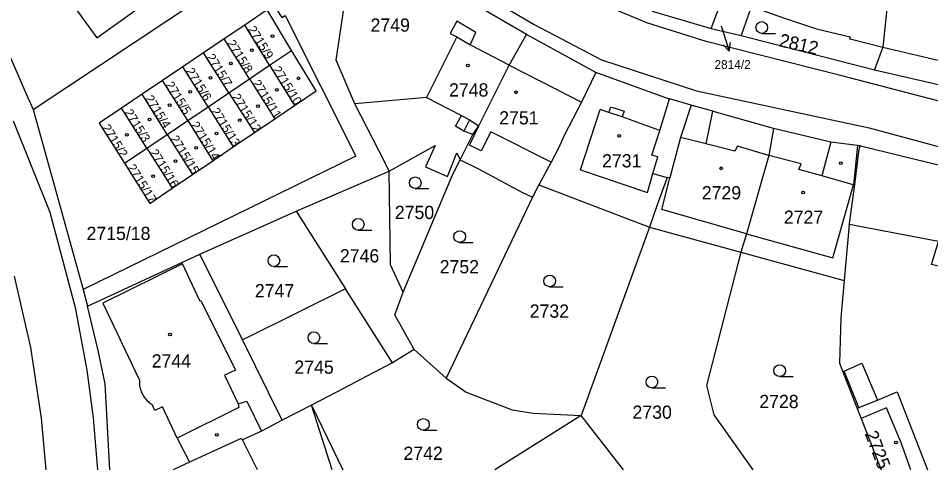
# Model space of a CAD drawing. Extents: x -527335 to -526256, y -1079142 to -1077809.
# Drawn here: x -527116.6 to -526999.4, y -1079141.5 to -1079083.6 of the extents above; entities that cross this region are included whole.
import ezdxf

# ---------------------------------------------------------------- set-up
doc = ezdxf.new("R2010")
doc.units = 0
for name, color, linetype in [('Vrstva 1', 7, 'Continuous'), ('Vrstva 2', 7, 'Continuous'), ('Vrstva 3', 7, 'Continuous'), ('Vrstva 4', 7, 'Continuous'), ('Vrstva 5', 7, 'Continuous'), ('Vrstva 7', 7, 'Continuous')]:
    doc.layers.add(name, color=color, linetype=linetype)

msp = doc.modelspace()

# ---------------------------------------------------------------- linework, layer by layer
at = {"layer": 'Vrstva 1'}
for p, q in [((-527027.56, -1079084.87), (-527026.14, -1079080.97)), ((-527035.15, -1079082.66), (-527027.56, -1079084.87)), ((-527022.5, -1079082.36), (-527023.73, -1079085.78)), ((-527087.52, -1079084.42), (-527090.18, -1079086.21)), ((-527084.33, -1079089.58), (-527087.52, -1079084.42)), ((-527027.56, -1079084.87), (-527023.73, -1079085.78)), ((-527090.18, -1079086.21), (-527092.83, -1079087.99)), ((-527086.93, -1079091.34), (-527090.18, -1079086.21)), ((-527053.53, -1079089.58), (-527051.3, -1079085.65)), ((-527042.41, -1079090.54), (-527051.3, -1079085.65)), ((-527023.73, -1079085.78), (-527006.59, -1079090.18)), ((-527084.33, -1079089.58), (-527081.51, -1079087.68)), ((-527092.83, -1079087.99), (-527095.49, -1079089.78)), ((-527089.56, -1079093.11), (-527092.83, -1079087.99)), ((-527095.49, -1079089.78), (-527098.1, -1079091.54)), ((-527092.24, -1079094.93), (-527095.49, -1079089.78)), ((-527086.93, -1079091.34), (-527084.33, -1079089.58)), ((-527084.33, -1079089.58), (-527081.13, -1079094.75)), ((-527089.56, -1079093.11), (-527086.93, -1079091.34)), ((-527086.93, -1079091.34), (-527083.68, -1079096.47)), ((-527098.1, -1079091.54), (-527100.72, -1079093.3)), ((-527094.86, -1079096.7), (-527098.1, -1079091.54)), ((-527100.72, -1079093.3), (-527103.37, -1079095.09)), ((-527097.49, -1079098.47), (-527100.72, -1079093.3)), ((-527092.24, -1079094.93), (-527089.56, -1079093.11)), ((-527089.56, -1079093.11), (-527086.28, -1079098.23)), ((-527083.68, -1079096.47), (-527081.13, -1079094.75)), ((-527114.75, -1079095.26), (-527108.32, -1079118.4)), ((-527100.12, -1079100.24), (-527103.37, -1079095.09)), ((-527094.86, -1079096.7), (-527092.24, -1079094.93)), ((-527092.24, -1079094.93), (-527089, -1079100.07)), ((-527097.49, -1079098.47), (-527094.86, -1079096.7)), ((-527094.86, -1079096.7), (-527091.63, -1079101.85)), ((-527086.28, -1079098.23), (-527083.68, -1079096.47)), ((-527089, -1079100.07), (-527086.28, -1079098.23)), ((-527100.12, -1079100.24), (-527097.49, -1079098.47)), ((-527097.49, -1079098.47), (-527094.26, -1079103.63)), ((-527102.99, -1079102.18), (-527100.12, -1079100.24)), ((-527100.12, -1079100.24), (-527096.87, -1079105.39)), ((-527091.63, -1079101.85), (-527089, -1079100.07)), ((-527094.26, -1079103.63), (-527091.63, -1079101.85)), ((-527096.87, -1079105.39), (-527094.26, -1079103.63)), ((-527080.91, -1079108.31), (-527068.95, -1079103.19)), ((-527049.72, -1079104.95), (-527050.56, -1079106.52)), ((-527049.72, -1079104.95), (-527035.52, -1079110.39)), ((-527050.56, -1079106.52), (-527061.66, -1079129.77)), ((-527080.91, -1079108.31), (-527074.57, -1079118.3)), ((-527009.82, -1079110.06), (-527010.5, -1079117.24)), ((-527035.52, -1079110.39), (-527044.28, -1079134.58)), ((-527035.52, -1079110.39), (-527023.76, -1079113.6)), ((-527023.76, -1079113.6), (-527010.5, -1079117.24)), ((-527107.73, -1079120.51), (-527093.31, -1079113.86)), ((-527087.83, -1079124.87), (-527093.31, -1079113.86)), ((-527068.54, -1079127.79), (-527074.57, -1079118.3)), ((-527108.32, -1079118.4), (-527107.73, -1079120.51)), ((-527082.7, -1079135.19), (-527087.83, -1079124.87)), ((-527065.77, -1079126.11), (-527068.54, -1079127.79)), ((-527061.66, -1079129.77), (-527065.77, -1079126.11)), ((-527078.96, -1079133.24), (-527082.7, -1079135.19)), ((-527076.3, -1079141.53), (-527078.96, -1079133.24)), ((-527078.96, -1079133.24), (-527074.91, -1079141.53)), ((-527044.28, -1079134.58), (-527055.39, -1079141.53)), ((-527042.15, -1079137.3), (-527044.28, -1079134.58)), ((-527008.8, -1079133.68), (-527008.31, -1079134.94)), ((-527008.31, -1079134.94), (-527005.73, -1079141.53)), ((-527038.84, -1079141.53), (-527042.15, -1079137.3))]:
    msp.add_line(p, q, dxfattribs=at)
for points in [[(-527175.94, -1079018.95), (-527174.51, -1079020.99), (-527170.88, -1079024.19), (-527166.19, -1079028.15), (-527156.94, -1079036.03), (-527151.99, -1079040.51), (-527144.47, -1079048.33), (-527131.02, -1079065.08), (-527128.12, -1079070.27), (-527126.15, -1079072.81), (-527121.46, -1079080.6), (-527119.15, -1079085.27), (-527115.79, -1079092.86), (-527114.75, -1079095.26)], [(-527117.52, -1079070.91), (-527112.81, -1079077.42), (-527111.7, -1079078.95), (-527106.54, -1079086.08), (-527097.38, -1079079.49), (-527102.75, -1079072.09), (-527104.98, -1079069.03), (-527108.4, -1079064.32), (-527113.48, -1079057.33), (-527115.7, -1079054.27), (-527119.42, -1079049.14)], [(-527017.49, -1079069.84), (-527011.34, -1079074.38), (-527006.77, -1079078.58), (-527004.82, -1079080.69), (-527005.52, -1079087.25)], [(-527073.4, -1079094.53), (-527075.8, -1079088.93), (-527073.64, -1079074.56), (-527071.09, -1079071.9)], [(-527051.3, -1079085.65), (-527059.51, -1079080.86), (-527065.39, -1079076.64), (-527071.09, -1079071.9)], [(-527114.75, -1079095.26), (-527093.11, -1079080.89), (-527091.79, -1079079.94), (-527087.05, -1079076.88), (-527082.75, -1079083.47), (-527082.32, -1079083.22), (-527073.26, -1079101.27), (-527108.32, -1079118.4)], [(-527081.51, -1079087.68), (-527084.66, -1079082.49), (-527087.52, -1079084.42)], [(-527022.39, -1079082.06), (-527018.27, -1079083.48), (-527014.05, -1079084.93), (-527009.72, -1079085.95), (-527009.78, -1079086.18), (-527009.52, -1079086.24), (-527005.52, -1079087.25)], [(-527053.53, -1079089.58), (-527058.56, -1079086.96), (-527057.82, -1079085.39), (-527060.29, -1079083.91), (-527061.12, -1079085.5), (-527060.26, -1079085.95), (-527064.15, -1079093.71), (-527073.4, -1079094.53)], [(-527081.13, -1079094.75), (-527078.36, -1079092.87), (-527081.51, -1079087.68)], [(-527005.52, -1079087.25), (-527006.5, -1079089.94), (-527006.59, -1079090.18)], [(-527059.85, -1079101.72), (-527058.21, -1079098.49), (-527057.45, -1079097.35), (-527053.53, -1079089.58)], [(-527006.59, -1079090.18), (-526994.63, -1079092.92), (-526991.9, -1079089.68)], [(-527042.41, -1079090.54), (-527044.26, -1079094.33), (-527046.46, -1079098.6), (-527047.21, -1079100.23), (-527048.16, -1079102.02), (-527049.72, -1079104.95)], [(-527030.16, -1079094.72), (-527032.95, -1079093.92), (-527033.07, -1079093.88), (-527042.41, -1079090.54)], [(-527068.95, -1079103.19), (-527069.52, -1079102.03), (-527073.4, -1079094.53)], [(-527030.16, -1079094.72), (-527031.52, -1079098.85), (-527032.88, -1079104.05), (-527033.22, -1079104), (-527034.51, -1079107.51), (-527035.52, -1079110.39)], [(-527019.56, -1079097.69), (-527027.13, -1079095.57), (-527027.36, -1079095.5), (-527030.01, -1079094.76), (-527030.16, -1079094.72)], [(-527103.37, -1079095.09), (-527106.24, -1079097.02), (-527102.99, -1079102.18)], [(-527019.56, -1079097.69), (-527020.17, -1079101.16), (-527023.05, -1079111.23), (-527023.76, -1079113.6)], [(-527008.36, -1079099.95), (-527008.58, -1079099.92), (-527008.77, -1079099.9), (-527012.21, -1079099.46), (-527012.36, -1079099.44), (-527019.56, -1079097.69)], [(-527068.95, -1079103.19), (-527063.07, -1079099.9), (-527064.28, -1079102.63), (-527061.45, -1079103.88), (-527060.28, -1079100.83), (-527059.85, -1079101.72)], [(-527009.82, -1079110.06), (-527009.8, -1079109.91), (-527009.1, -1079104.91), (-527008.55, -1079100.34), (-527008.36, -1079099.95)], [(-527008.36, -1079099.95), (-526996.25, -1079102.89), (-526987.44, -1079105.14), (-526984.58, -1079106.98)], [(-527067.18, -1079118.75), (-527060.79, -1079103.58), (-527059.85, -1079101.72)], [(-527059.85, -1079101.72), (-527057.47, -1079102.88), (-527051.9, -1079105.88), (-527050.56, -1079106.52)], [(-527102.99, -1079102.18), (-527099.75, -1079107.33), (-527096.87, -1079105.39)], [(-527067.18, -1079118.75), (-527068.78, -1079115.24), (-527068.95, -1079103.19)], [(-527093.31, -1079113.86), (-527085.79, -1079110.53), (-527080.91, -1079108.31)], [(-526971.93, -1079115.94), (-526976.33, -1079115.57), (-526988.12, -1079117.78), (-526988.51, -1079117.72), (-526989.62, -1079117.54), (-526999.27, -1079115.18), (-526998.37, -1079112.24), (-527009.82, -1079110.06)], [(-527023.76, -1079113.6), (-527028.19, -1079130.73), (-527027.25, -1079134.48), (-527022.21, -1079141.53)], [(-527074.57, -1079118.3), (-527086.94, -1079124.43), (-527087.83, -1079124.87)], [(-527010.5, -1079117.24), (-527010.9, -1079122.03), (-527011.07, -1079127.87), (-527008.8, -1079133.68)], [(-527065.77, -1079126.11), (-527068.26, -1079121.64), (-527067.18, -1079118.75)], [(-527104.87, -1079141.53), (-527105.47, -1079130.49), (-527106.38, -1079126.22), (-527107.73, -1079120.51)], [(-527068.54, -1079127.79), (-527071.12, -1079129.14), (-527074.77, -1079131.05), (-527078.96, -1079133.24)], [(-527061.66, -1079129.77), (-527059.09, -1079131.59), (-527053.17, -1079133.84), (-527050.44, -1079134.25), (-527044.28, -1079134.58)], [(-527008.8, -1079133.68), (-527008.59, -1079133.56), (-527006.18, -1079132.58), (-527003.65, -1079131.52), (-526999.76, -1079141.53)], [(-527001.89, -1079141.53), (-527003.17, -1079138.09), (-527005.05, -1079133.57), (-527008.31, -1079134.94)], [(-527082.7, -1079135.19), (-527085.39, -1079136.6), (-527087.84, -1079137.7), (-527088, -1079137.51), (-527094.65, -1079140.58), (-527096.75, -1079141.53)]]:
    msp.add_lwpolyline(points, dxfattribs=at)
at = {"layer": 'Vrstva 3'}
for p, q in [((-527021.07, -1079085.49), (-527019.32, -1079085.49)), ((-527065.61, -1079105.43), (-527063.86, -1079105.43)), ((-527072.94, -1079110.77), (-527071.19, -1079110.77)), ((-527059.91, -1079112.34), (-527058.16, -1079112.34)), ((-527083.79, -1079115.43), (-527082.04, -1079115.43)), ((-527048.34, -1079118.04), (-527046.59, -1079118.04)), ((-527078.64, -1079125.32), (-527076.89, -1079125.32)), ((-527018.77, -1079129.56), (-527017.02, -1079129.56)), ((-527035.19, -1079131.02), (-527033.44, -1079131.02)), ((-527064.58, -1079136.47), (-527062.83, -1079136.47))]:
    msp.add_line(p, q, dxfattribs=at)
for centre in [(-527021.07, -1079084.74), (-527065.61, -1079104.68), (-527072.94, -1079110.02), (-527059.91, -1079111.59), (-527083.79, -1079114.68), (-527048.34, -1079117.29), (-527078.64, -1079124.57), (-527018.77, -1079128.81), (-527035.19, -1079130.27), (-527064.58, -1079135.72)]:
    msp.add_circle(centre, 0.75, dxfattribs=at)
at = {"layer": 'Vrstva 4'}
for p, q in [((-527058.51, -1079079.53), (-527050.31, -1079084.34)), ((-527035.83, -1079084.12), (-527043.03, -1079081.09)), ((-527028.2, -1079086.55), (-527035.83, -1079084.12)), ((-527050.31, -1079084.34), (-527041.68, -1079088.91)), ((-527060.26, -1079085.95), (-527058.56, -1079086.96)), ((-527010.79, -1079090.93), (-527028.2, -1079086.55)), ((-527005.52, -1079087.25), (-526998.21, -1079088.98)), ((-527041.68, -1079088.91), (-527029.48, -1079092.89)), ((-527053.53, -1079089.58), (-527047.35, -1079092.75)), ((-526994.16, -1079095.3), (-527010.79, -1079090.93)), ((-527047.35, -1079092.75), (-527044.26, -1079094.33)), ((-527029.48, -1079092.89), (-527007.27, -1079097.63)), ((-527064.15, -1079093.71), (-527059.66, -1079096.06)), ((-527034.16, -1079097.97), (-527032.95, -1079093.92)), ((-527044.36, -1079103.01), (-527041.85, -1079095.25)), ((-527040.71, -1079095.64), (-527041.85, -1079095.25)), ((-527040.71, -1079095.64), (-527040.46, -1079094.96)), ((-527040.46, -1079095.73), (-527040.71, -1079095.64)), ((-527040.46, -1079094.96), (-527040.23, -1079095.03)), ((-527039.29, -1079096.14), (-527040.46, -1079095.73)), ((-527040.23, -1079095.03), (-527039.01, -1079095.42)), ((-527038.77, -1079095.5), (-527039.02, -1079096.23)), ((-527039.01, -1079095.42), (-527038.77, -1079095.5)), ((-527028.22, -1079099.7), (-527027.36, -1079095.5)), ((-527117.32, -1079096.72), (-527112.58, -1079108.47)), ((-527060.45, -1079097.43), (-527059.66, -1079096.06)), ((-527059.66, -1079096.06), (-527058.66, -1079096.58)), ((-527058.66, -1079096.58), (-527059.35, -1079098.07)), ((-527058.66, -1079096.58), (-527057.45, -1079097.35)), ((-527039.02, -1079096.23), (-527039.29, -1079096.14)), ((-527034.3, -1079097.92), (-527039.02, -1079096.23)), ((-527059.35, -1079098.07), (-527060.45, -1079097.43)), ((-527058.21, -1079098.49), (-527059.35, -1079098.07)), ((-527058.65, -1079099.84), (-527057.45, -1079097.35)), ((-527055.88, -1079098.14), (-527057.14, -1079100.6)), ((-527048.16, -1079102.02), (-527055.88, -1079098.14)), ((-527035.22, -1079101.14), (-527034.16, -1079097.97)), ((-527034.3, -1079097.92), (-527034.16, -1079097.97)), ((-527007.27, -1079097.63), (-526996.46, -1079100.53)), ((-527031.35, -1079098.89), (-527031.52, -1079098.85)), ((-527028.22, -1079099.7), (-527031.35, -1079098.89)), ((-527012.21, -1079099.46), (-527013.34, -1079103.8)), ((-527057.14, -1079100.6), (-527058.65, -1079099.84)), ((-527028.07, -1079099.74), (-527028.22, -1079099.7)), ((-527024.55, -1079100.64), (-527028.07, -1079099.74)), ((-527024.19, -1079099.96), (-527024.55, -1079100.64)), ((-527020.17, -1079101.16), (-527024.19, -1079099.96)), ((-527008.77, -1079099.9), (-527009.28, -1079104.94)), ((-527034.45, -1079101.35), (-527035.22, -1079101.14)), ((-527035.06, -1079103.47), (-527034.45, -1079101.35)), ((-527016, -1079102.26), (-527020.17, -1079101.16)), ((-527044.36, -1079103.01), (-527035.77, -1079105.93)), ((-527016.3, -1079102.96), (-527016, -1079102.26)), ((-527013.46, -1079103.76), (-527016.3, -1079102.96)), ((-527035.77, -1079105.93), (-527035.06, -1079103.47)), ((-527035.06, -1079103.47), (-527033.22, -1079104)), ((-527033.92, -1079108.11), (-527032.88, -1079104.05)), ((-527013.34, -1079103.8), (-527013.46, -1079103.76)), ((-527009.28, -1079104.94), (-527013.34, -1079103.8)), ((-527011.92, -1079114.33), (-527009.28, -1079104.94)), ((-527009.28, -1079104.94), (-527009.1, -1079104.91)), ((-527112.58, -1079108.47), (-527109.31, -1079120.7)), ((-527023.05, -1079111.23), (-527033.92, -1079108.11)), ((-527023.05, -1079111.23), (-527011.92, -1079114.33)), ((-527095.53, -1079115.09), (-527105.76, -1079120.14)), ((-527093.31, -1079119.84), (-527095.53, -1079115.09)), ((-527115.04, -1079125.83), (-527117.11, -1079116.67)), ((-527105.76, -1079120.14), (-527103.56, -1079124.79)), ((-527093.31, -1079119.84), (-527093.19, -1079119.8)), ((-527093.19, -1079119.8), (-527088.74, -1079128.74)), ((-527109.31, -1079120.7), (-527107.85, -1079128.75)), ((-527103.34, -1079125.25), (-527103.56, -1079124.79)), ((-527101.06, -1079129.97), (-527103.34, -1079125.25)), ((-527113.64, -1079134.93), (-527115.04, -1079125.83)), ((-527107.85, -1079128.75), (-527107.02, -1079134.86)), ((-527088.74, -1079128.74), (-527090.12, -1079129.4)), ((-527010.5, -1079128.87), (-527008.19, -1079127.87)), ((-527008.59, -1079133.56), (-527010.5, -1079128.87)), ((-527008.19, -1079127.87), (-527006.18, -1079132.58)), ((-527090.12, -1079129.4), (-527088.37, -1079133.08)), ((-527099.07, -1079133.93), (-527099.45, -1079133.15)), ((-527098.09, -1079133.47), (-527099.07, -1079133.93)), ((-527096.23, -1079137.48), (-527098.09, -1079133.47)), ((-527088.29, -1079133.55), (-527096.23, -1079137.48)), ((-527088.37, -1079133.08), (-527087.25, -1079132.71)), ((-527088.37, -1079133.08), (-527088.29, -1079133.55)), ((-527087.25, -1079132.71), (-527085.39, -1079136.6)), ((-527113.06, -1079141.53), (-527113.64, -1079134.93)), ((-527107.02, -1079134.86), (-527106.47, -1079141.53)), ((-527096.23, -1079137.48), (-527094.65, -1079140.58)), ((-527085.91, -1079141.53), (-527087.84, -1079137.7))]:
    msp.add_line(p, q, dxfattribs=at)
msp.add_lwpolyline([(-527101.06, -1079129.97), (-527101.07, -1079130.13), (-527101.07, -1079130.28), (-527101.07, -1079130.44), (-527101.06, -1079130.6), (-527101.04, -1079130.75), (-527101.02, -1079130.91), (-527100.98, -1079131.06), (-527100.95, -1079131.21), (-527100.9, -1079131.36), (-527100.84, -1079131.51), (-527100.78, -1079131.65), (-527100.72, -1079131.79), (-527100.64, -1079131.93), (-527100.56, -1079132.07), (-527100.47, -1079132.2), (-527100.38, -1079132.32), (-527100.28, -1079132.45), (-527100.18, -1079132.56), (-527100.07, -1079132.67), (-527099.95, -1079132.78), (-527099.84, -1079132.88), (-527099.71, -1079132.98), (-527099.58, -1079133.07), (-527099.45, -1079133.15)], dxfattribs=at)
at = {"layer": 'Vrstva 5'}
for centre in [(-527083.98, -1079085.84), (-527086.63, -1079087.65), (-527089.31, -1079089.38), (-527058.84, -1079089.61), (-527091.95, -1079091.2), (-527080.62, -1079091.27), (-527094.54, -1079092.99), (-527083.4, -1079092.75), (-527052.66, -1079093.07), (-527097.18, -1079094.72), (-527085.83, -1079094.84), (-527099.79, -1079096.57), (-527088.18, -1079096.65), (-527102.68, -1079098.52), (-527091.16, -1079098.37), (-527039.39, -1079098.65), (-527093.77, -1079100.18), (-527096.42, -1079101.91), (-527026.3, -1079102.83), (-527010.9, -1079102.18), (-527099.31, -1079103.82), (-527015.76, -1079105.92), (-527097.14, -1079124.16), (-527091.12, -1079137.05), (-527003.82, -1079138.05)]:
    msp.add_circle(centre, 0.175, dxfattribs=at)
at = {"layer": 'Vrstva 7'}
for p, q in [((-527026.27, -1079084.53), (-527026.16, -1079084.91)), ((-527026.16, -1079084.91), (-527025.28, -1079087.78)), ((-527025.28, -1079087.78), (-527026.05, -1079086.97)), ((-527025.28, -1079087.78), (-527025.1, -1079086.68))]:
    msp.add_line(p, q, dxfattribs=at)

# ---------------------------------------------------------------- texts
at = {"layer": 'Vrstva 2'}
for s, height, p in [('2749', 1.7, (-527071.36, -1079085.28)), ('2814/2', 1.14, (-527027.15, -1079090.07)), ('2748', 1.7, (-527061.27, -1079093.61)), ('2751', 1.7, (-527054.82, -1079097.19)), ('2731', 1.7, (-527041.6, -1079102.71)), ('2729', 1.7, (-527028.78, -1079106.81)), ('2750', 1.7, (-527068.24, -1079109.34)), ('2727', 1.7, (-527018.23, -1079109.95)), ('2715/18', 1.7, (-527107.87, -1079112.03)), ('2746', 1.7, (-527075.3, -1079114.91)), ('2752', 1.7, (-527062.47, -1079116.31)), ('2747', 1.7, (-527086.23, -1079119.39)), ('2732', 1.7, (-527050.9, -1079122.01)), ('2744', 1.7, (-527099.49, -1079128.41)), ('2745', 1.7, (-527081.15, -1079129.21)), ('2728', 1.7, (-527021.39, -1079133.62)), ('2730', 1.7, (-527037.69, -1079134.99)), ('2742', 1.7, (-527067.13, -1079140.27))]:
    msp.add_text(s, height=height, dxfattribs=at).set_placement(p)
for s, height, rotation, p in [('2715/9', 1.14, 302, (-527087.19, -1079084.98)), ('2715/8', 1.14, 302, (-527089.85, -1079086.77)), ('2812', 1.7, 347, (-527018.95, -1079087.14)), ('2715/7', 1.14, 302, (-527092.5, -1079088.55)), ('2715/6', 1.14, 302, (-527095.16, -1079090.34)), ('2715/10', 1.14, 302, (-527084, -1079090.14)), ('2715/5', 1.14, 302, (-527097.77, -1079092.1)), ('2715/11', 1.14, 302, (-527086.6, -1079091.9)), ('2715/4', 1.14, 302, (-527100.39, -1079093.86)), ('2715/12', 1.14, 302, (-527089.23, -1079093.67)), ('2715/3', 1.14, 302, (-527103.04, -1079095.65)), ('2715/13', 1.14, 302, (-527091.91, -1079095.49)), ('2715/2', 1.14, 302, (-527105.92, -1079097.61)), ('2715/14', 1.14, 302, (-527094.53, -1079097.26)), ('2715/15', 1.14, 302, (-527097.16, -1079099.03)), ('2715/16', 1.14, 302, (-527099.79, -1079100.8)), ('2715/17', 1.14, 302, (-527102.66, -1079102.74)), ('2725', 1.7, 291, (-527007.86, -1079136.9))]:
    msp.add_text(s, height=height, rotation=rotation, dxfattribs=at).set_placement(p)

doc.saveas('drawing.dxf')
